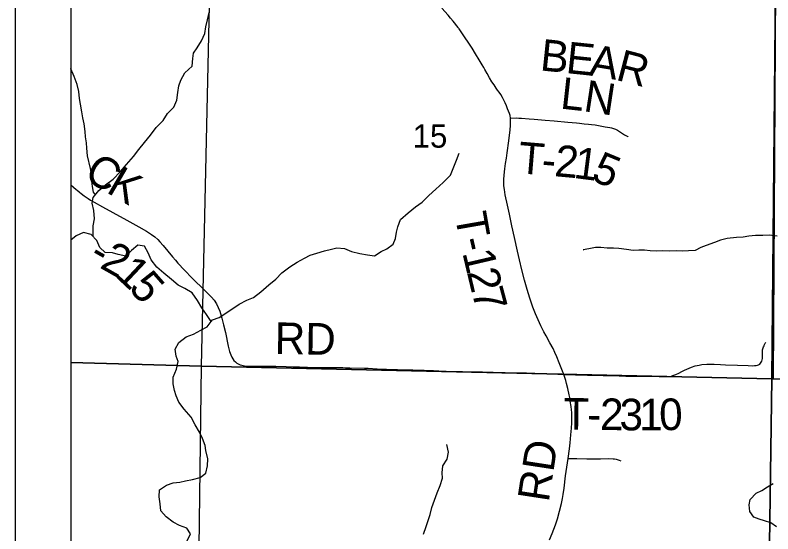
# Model space of a CAD drawing. Extents: x 0 to 34, y 0 to 22.
# Drawn here: x 2 to 3.363, y 18.422 to 19.354 of the extents above; entities that cross this region are included whole.
import ezdxf

# ---------------------------------------------------------------- set-up
doc = ezdxf.new("R2010")
doc.units = 0
for name, color, linetype in [('GM_X_Corporation', 7, 'Continuous'), ('GM_X_Minor_River', 7, 'Continuous'), ('GM_X_Section_Text', 7, 'Continuous'), ('GM_X_Township_Road', 7, 'Continuous'), ('GM_X_Township_Road_Text', 7, 'Continuous'), ('SH_Data', 7, 'Continuous')]:
    doc.layers.add(name, color=color, linetype=linetype)

msp = doc.modelspace()

# ---------------------------------------------------------------- linework, layer by layer
at = {"layer": 'GM_X_Corporation'}
for points in [[(8.9, 20.9), (2.1, 20.9), (2.1, 15.6606)], [(5.3543, 16.3597), (5.3699, 17.5116), (5.3717, 17.6123), (4.6401, 17.6298), (4.3705, 17.6391), (4.3669, 17.8198), (4.37, 17.9048), (4.3768, 18.4091), (4.3782, 18.6502), (4.377, 18.6713), (3.7035, 18.69), (3.3642, 18.7005), (3.3691, 19.5041), (3.3724, 19.7263), (3.3869, 20.7918), (3.3886, 20.9), (2.1, 20.9), (2.1, 15.6606)]]:
    msp.add_lwpolyline(points, dxfattribs=at)
for points in [[(2.1, 19.7588), (2.1, 18.7299), (2.3352, 18.7231), (2.3578, 19.7506)], [(3.3708, 19.7265), (3.3614, 18.7006), (2.3352, 18.7231), (2.3578, 19.7506)], [(4.3939, 19.6935), (4.3772, 18.6714), (3.3614, 18.7006), (3.3708, 19.7265)], [(2.1, 18.7299), (2.1, 17.7065), (2.3219, 17.7003), (2.3352, 18.7231)], [(2.3352, 18.7231), (3.3614, 18.7006), (3.3465, 17.6805), (2.3219, 17.7003)], [(4.3772, 18.6714), (4.3675, 17.6365), (3.3465, 17.6805), (3.3614, 18.7006)]]:
    msp.add_lwpolyline(points, close=True, dxfattribs=at)
at = {"layer": 'GM_X_Minor_River'}
for points in [[(2.1406, 18.956), (2.1402, 18.9639), (2.1401, 18.9756), (2.1427, 18.9882), (2.1414, 19.0026), (2.1387, 19.0162), (2.1405, 19.0261), (2.1507, 19.0387), (2.1624, 19.049), (2.1763, 19.0594), (2.1887, 19.0724), (2.2, 19.0854), (2.2128, 19.0999), (2.2222, 19.1125), (2.2324, 19.1254), (2.2436, 19.1384), (2.2538, 19.1518), (2.2662, 19.1644), (2.2741, 19.1773), (2.2854, 19.1888), (2.2906, 19.2014), (2.2924, 19.2147), (2.2946, 19.2272), (2.2983, 19.2371), (2.3051, 19.2504), (2.3182, 19.2623), (2.3197, 19.276), (2.3207, 19.2854), (2.3275, 19.295), (2.3354, 19.3076), (2.3414, 19.3209), (2.3428, 19.333), (2.3461, 19.3456), (2.3487, 19.3589)], [(2.1446, 19.0311), (2.1412, 19.0356), (2.1393, 19.0458), (2.1381, 19.0557), (2.1372, 19.0686), (2.1356, 19.0785), (2.1302, 19.1012), (2.1289, 19.1149), (2.1285, 19.1243), (2.1265, 19.1353), (2.1257, 19.1448), (2.1241, 19.1589), (2.1217, 19.1695), (2.1198, 19.1805), (2.1174, 19.1941), (2.1158, 19.2044), (2.1146, 19.2169), (2.1118, 19.2294), (2.1064, 19.2438), (2.1003, 19.2574), (2.1, 19.2581)], [(2.3528, 18.8036), (2.3547, 18.8063), (2.3672, 18.8105), (2.3932, 18.8282), (2.403, 18.8343), (2.4166, 18.8416), (2.4287, 18.8466), (2.4419, 18.8566), (2.4563, 18.8692), (2.4691, 18.8792), (2.48, 18.891), (2.4943, 18.9014), (2.5072, 18.9098), (2.5204, 18.9175), (2.5306, 18.9225), (2.5427, 18.9264), (2.5563, 18.9306), (2.5688, 18.9334), (2.5786, 18.9357), (2.5923, 18.9347), (2.6052, 18.9291), (2.62, 18.9254), (2.6341, 18.9232), (2.6466, 18.9214), (2.6587, 18.929), (2.6685, 18.9337), (2.6798, 18.9425), (2.6843, 18.9527), (2.6861, 18.9638), (2.6883, 18.9736), (2.6932, 18.9866), (2.7067, 18.9988), (2.7199, 19.0092), (2.7324, 19.0176), (2.7441, 19.0298), (2.7565, 19.0413), (2.7697, 19.0531), (2.7829, 19.0661), (2.7881, 19.0783), (2.7937, 19.0932), (2.7985, 19.1061)], [(2.3093, 18.4089), (2.3152, 18.4219), (2.3087, 18.4321), (2.2958, 18.4369), (2.284, 18.4429), (2.2718, 18.452), (2.2623, 18.4633), (2.2607, 18.4754), (2.2591, 18.4879), (2.2597, 18.5008), (2.2722, 18.5093), (2.2843, 18.5135), (2.2964, 18.5148), (2.3066, 18.5167), (2.3191, 18.5195), (2.3327, 18.523), (2.3433, 18.531), (2.3459, 18.5439), (2.3465, 18.5565), (2.343, 18.5712), (2.3418, 18.5807), (2.3372, 18.5928), (2.3318, 18.6046), (2.3238, 18.6178), (2.3165, 18.6314), (2.3042, 18.6458), (2.2943, 18.6586), (2.2897, 18.6696), (2.2866, 18.6794), (2.2842, 18.6912), (2.2841, 18.7033), (2.2905, 18.7174), (2.293, 18.7315), (2.2896, 18.7413), (2.2876, 18.7534), (2.2947, 18.7656), (2.3079, 18.776), (2.3208, 18.7806), (2.334, 18.7879), (2.3457, 18.7937), (2.3528, 18.8036), (2.344, 18.8161), (2.336, 18.8282), (2.3283, 18.8414), (2.3187, 18.8546), (2.3054, 18.8629), (2.2932, 18.8689), (2.281, 18.8787), (2.2677, 18.89), (2.2547, 18.9013), (2.2448, 18.9141), (2.2394, 18.927), (2.2329, 18.9387), (2.2207, 18.9405), (2.209, 18.9309), (2.1989, 18.9206), (2.1856, 18.9239), (2.1753, 18.9269), (2.162, 18.9276), (2.1521, 18.9366), (2.1471, 18.9491), (2.1368, 18.96), (2.1231, 18.9634), (2.1095, 18.9572), (2.1, 18.9493)], [(3.3708, 18.9566), (3.3561, 18.9584), (3.3447, 18.9579), (3.3319, 18.9581), (3.3198, 18.9565), (3.3096, 18.9548), (3.2975, 18.9543), (3.2809, 18.9523), (3.2688, 18.9495), (3.2583, 18.9452), (3.2432, 18.9401), (3.2334, 18.9366), (3.2232, 18.9312), (3.2115, 18.9303), (3.2009, 18.9298), (3.1904, 18.9301), (3.1775, 18.93), (3.1647, 18.9302), (3.1541, 18.9297), (3.142, 18.9303), (3.1321, 18.9314), (3.1219, 18.9313), (3.1117, 18.9308), (3.0996, 18.9326), (3.086, 18.9343), (3.0762, 18.9353), (3.0648, 18.9352), (3.0538, 18.9362), (3.044, 18.9361), (3.0319, 18.9337), (3.0217, 18.9321), (3.0221, 18.9321)], [(2.7345, 18.4213), (2.7394, 18.4346), (2.7435, 18.4472), (2.7468, 18.4567), (2.7498, 18.4692), (2.7546, 18.4825), (2.7591, 18.4955), (2.7643, 18.5088), (2.7687, 18.5217), (2.7679, 18.5316), (2.7693, 18.5441), (2.7772, 18.556), (2.7794, 18.5685), (2.7767, 18.5821)], [(3.3693, 18.4342), (3.3594, 18.4412), (3.3477, 18.4449), (3.3382, 18.4478), (3.3287, 18.4515), (3.3218, 18.4621), (3.3206, 18.4738), (3.3224, 18.4833), (3.3329, 18.4948), (3.3434, 18.4998), (3.3536, 18.506), (3.3634, 18.5121)]]:
    msp.add_lwpolyline(points, dxfattribs=at)
at = {"layer": 'GM_X_Township_Road'}
for points in [[(2.8913, 19.1689), (2.8904, 19.1736), (2.8891, 19.1773), (2.8856, 19.1858), (2.8836, 19.1908), (2.8813, 19.1966), (2.8792, 19.2011), (2.8767, 19.206), (2.8735, 19.2113), (2.8707, 19.2154), (2.8678, 19.2194), (2.8653, 19.2229), (2.8614, 19.2285), (2.8577, 19.2342), (2.8535, 19.2411), (2.8489, 19.2492), (2.8451, 19.2563), (2.8431, 19.2602), (2.8402, 19.265), (2.8348, 19.274), (2.8283, 19.2846), (2.822, 19.2946), (2.8172, 19.3019), (2.8073, 19.3169), (2.7988, 19.3292), (2.7977, 19.3307), (2.7969, 19.3316), (2.7879, 19.3435), (2.7833, 19.3485), (2.7788, 19.3537), (2.7674, 19.3668)], [(2.987, 18.7079), (2.9787, 18.729), (2.9743, 18.7399), (2.9708, 18.7479), (2.9676, 18.7546), (2.9621, 18.7651), (2.9551, 18.7775), (2.9513, 18.7846), (2.9456, 18.7957), (2.9406, 18.8064), (2.936, 18.8172), (2.9313, 18.8294), (2.9258, 18.8453), (2.921, 18.8607), (2.9162, 18.8774), (2.9114, 18.896), (2.907, 18.9141), (2.9035, 18.9299), (2.8985, 18.9542), (2.8937, 18.9754), (2.889, 18.996), (2.8855, 19.0124), (2.8817, 19.0313), (2.8801, 19.0405), (2.8793, 19.0472), (2.879, 19.0534), (2.8789, 19.0584), (2.8794, 19.0664), (2.8806, 19.0775), (2.8821, 19.0873), (2.8836, 19.097), (2.8851, 19.1066), (2.8881, 19.1281), (2.8905, 19.1479), (2.8911, 19.1559), (2.8911, 19.1609), (2.8913, 19.1689)], [(2.8913, 19.1689), (2.9013, 19.1692), (2.9059, 19.1691), (2.9109, 19.1687), (2.9245, 19.1676), (2.9337, 19.167), (2.9536, 19.1654), (2.9697, 19.1641), (2.9758, 19.1636), (2.9882, 19.1625), (2.9944, 19.1618), (3.0018, 19.1611), (3.0098, 19.1603), (3.0154, 19.1598), (3.0234, 19.1589), (3.0315, 19.1581), (3.037, 19.1574), (3.0432, 19.1567), (3.0493, 19.1556), (3.0554, 19.1547), (3.0615, 19.1534), (3.07, 19.1518), (3.0725, 19.1513), (3.0761, 19.1504), (3.0802, 19.1492), (3.0836, 19.1475), (3.0856, 19.1462), (3.0906, 19.1424), (3.0964, 19.1389), (3.1019, 19.136), (3.103, 19.1355)], [(2.1, 19.0491), (2.1004, 19.0489), (2.1097, 19.0408), (2.1116, 19.0392), (2.115, 19.0364), (2.116, 19.0357), (2.1189, 19.0334), (2.1243, 19.0293), (2.1314, 19.0243), (2.1356, 19.0217), (2.1421, 19.0179), (2.1574, 19.0097), (2.1759, 18.9995), (2.201, 18.9858), (2.2227, 18.9738), (2.2362, 18.966), (2.2455, 18.9599), (2.2514, 18.9553), (2.2564, 18.9507), (2.2604, 18.9467), (2.2662, 18.9402), (2.2831, 18.9196), (2.2883, 18.9134), (2.2929, 18.9083), (2.3048, 18.8956), (2.3187, 18.8815), (2.3414, 18.8593), (2.3479, 18.8527), (2.353, 18.8472), (2.3577, 18.8415), (2.3619, 18.8353), (2.3652, 18.8286), (2.3679, 18.8217), (2.3717, 18.8092), (2.375, 18.7972), (2.3783, 18.7833), (2.3834, 18.759), (2.3858, 18.7493), (2.3878, 18.7435), (2.3895, 18.7395), (2.3914, 18.7362), (2.3936, 18.7333), (2.3962, 18.7306), (2.3986, 18.7287), (2.4013, 18.7271), (2.4047, 18.7256), (2.4076, 18.7247), (2.4125, 18.7238), (2.4174, 18.7233), (2.4236, 18.7231), (2.4404, 18.7232), (2.4497, 18.7233), (2.469, 18.723), (2.4876, 18.7225), (2.4993, 18.7221), (2.5117, 18.7217), (2.5196, 18.7214), (2.5257, 18.721), (2.5367, 18.7208), (2.5398, 18.7207), (2.5571, 18.7205), (2.5657, 18.7205), (2.5805, 18.7205), (2.5892, 18.7204), (2.5942, 18.7202), (2.6022, 18.72), (2.6283, 18.7196), (2.6351, 18.7193), (2.6513, 18.7184), (2.668, 18.7176), (2.6879, 18.7169), (2.7015, 18.7165), (2.7071, 18.7163), (2.7151, 18.7162), (2.7251, 18.7159), (2.7356, 18.7157), (2.7523, 18.715), (2.7623, 18.7146), (2.7753, 18.7142), (2.7908, 18.7136), (2.8045, 18.7132), (2.823, 18.7128), (2.8354, 18.7127), (2.8404, 18.7126), (2.8478, 18.7125), (2.8527, 18.7123), (2.8596, 18.712), (2.8812, 18.7115), (2.8974, 18.7113), (2.9197, 18.711), (2.9655, 18.7091), (2.987, 18.7079)], [(2.987, 18.7079), (2.9978, 18.7078), (3.0077, 18.7076), (3.0189, 18.7073), (3.0294, 18.707), (3.058, 18.7061), (3.0865, 18.7054), (3.0983, 18.7051), (3.1088, 18.7051), (3.1163, 18.7051), (3.1372, 18.7052), (3.1586, 18.7044), (3.1678, 18.7043), (3.1733, 18.7043), (3.1776, 18.7047), (3.1805, 18.7053), (3.183, 18.706), (3.1882, 18.7079), (3.1938, 18.7105), (3.1993, 18.7133), (3.2043, 18.7159), (3.2122, 18.7195), (3.2168, 18.7213), (3.2233, 18.7234), (3.2305, 18.725), (3.2354, 18.7258), (3.244, 18.7266), (3.2521, 18.7267), (3.2577, 18.7264), (3.2688, 18.726), (3.2781, 18.7257), (3.2992, 18.7248), (3.3185, 18.7242), (3.3266, 18.7239), (3.3297, 18.724), (3.3327, 18.7241), (3.3353, 18.7246), (3.3374, 18.7254), (3.3394, 18.7269), (3.3408, 18.7284), (3.3421, 18.7304), (3.3429, 18.7322), (3.3436, 18.7345), (3.3441, 18.7369), (3.3443, 18.7388), (3.3444, 18.7425), (3.3442, 18.7468), (3.3442, 18.7499), (3.3443, 18.7513), (3.3445, 18.7523), (3.3449, 18.7541), (3.3461, 18.7576), (3.3471, 18.7599), (3.3482, 18.7621), (3.3494, 18.7642), (3.3506, 18.7656)], [(2.9946, 18.557), (2.997, 18.5745), (2.9982, 18.585), (2.9997, 18.5998), (3.0005, 18.6115), (3.0012, 18.6215), (3.0013, 18.6344), (3.0011, 18.6397), (3.0008, 18.6444), (3.0002, 18.6506), (2.9986, 18.6604), (2.9976, 18.6665), (2.9966, 18.6714), (2.994, 18.6829), (2.992, 18.692), (2.9905, 18.6974), (2.9888, 18.7027), (2.987, 18.7079)], [(2.9613, 18.4107), (2.9662, 18.4221), (2.9693, 18.4302), (2.972, 18.4379), (2.9754, 18.4485), (2.9792, 18.4623), (2.9827, 18.4761), (2.9846, 18.4852), (2.9859, 18.4926), (2.9874, 18.5037), (2.9902, 18.5259), (2.9946, 18.557)], [(2.9946, 18.557), (3.0101, 18.5572), (3.0281, 18.5568), (3.0411, 18.5567), (3.0529, 18.5568), (3.0665, 18.5569), (3.0758, 18.5566), (3.0783, 18.5564), (3.0813, 18.5557), (3.0865, 18.5539), (3.0894, 18.5528)]]:
    msp.add_lwpolyline(points, dxfattribs=at)
at = {"layer": 'SH_Data'}
for p, q in [((2, 21), (2, 14)), ((2.1, 20.9), (2.1, 14.1))]:
    msp.add_line(p, q, dxfattribs=at)

# ---------------------------------------------------------------- texts
at = {"layer": 'GM_X_Section_Text'}
msp.add_text('15', height=0.04186, rotation=0, dxfattribs=at).set_placement((2.7151, 19.1158))
at = {"layer": 'GM_X_Township_Road_Text'}
for s, height, rotation, p in [('B', 0.0568, 354.1038, (2.9429, 19.2549)), ('E', 0.0568, 354.1046, (2.9893, 19.2501)), ('A', 0.0568, 350.6754, (3.0307, 19.2459)), ('R', 0.0568, 345.3854, (3.0786, 19.2381)), ('L', 0.0568, 353.6548, (2.9792, 19.1863)), ('N', 0.0568, 351.2929, (3.0208, 19.1817)), ('T', 0.0568, 355.2549, (2.9034, 19.0701)), ('2', 0.0568, 354.8072, (2.9689, 19.0647)), ('1', 0.0568, 352.6471, (3.0031, 19.0616)), ('C', 0.0568, 328.9025, (2.1214, 19.061)), ('5', 0.0568, 337.6536, (3.0341, 19.0581)), ('K', 0.0568, 329.5954, (2.162, 19.0365)), ('-', 0.0568, 355.1819, (2.9457, 19.0666)), ('T', 0.0568, 279.9714, (2.7908, 18.9951)), ('-', 0.0568, 283.2033, (2.7989, 18.9499)), ('-', 0.0568, 330.669, (2.13, 18.9124)), ('2', 0.0568, 330.5269, (2.1503, 18.901)), ('1', 0.0568, 283.1887, (2.8042, 18.9272)), ('1', 0.0568, 316.7629, (2.1779, 18.886)), ('5', 0.0568, 311.2662, (2.2024, 18.863)), ('2', 0.0568, 283.4081, (2.8123, 18.8928)), ('7', 0.0568, 284.9397, (2.8208, 18.8572)), ('RD', 0.05682, 359.024, (2.4665, 18.7451)), ('T', 0.0568, 359.2993, (2.986, 18.6092)), ('2', 0.0568, 359.3203, (3.0518, 18.6084)), ('3', 0.0568, 359.474, (3.087, 18.6079)), ('1', 0.0568, 359.9802, (3.1225, 18.6076)), ('0', 0.0568, 1.5368, (3.1592, 18.6076)), ('-', 0.0568, 359.2974, (3.0285, 18.6086)), ('RD', 0.05682, 81.3193, (2.9597, 18.4772))]:
    msp.add_text(s, height=height, rotation=rotation, dxfattribs=at).set_placement(p)

doc.saveas('drawing.dxf')
